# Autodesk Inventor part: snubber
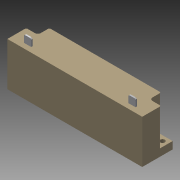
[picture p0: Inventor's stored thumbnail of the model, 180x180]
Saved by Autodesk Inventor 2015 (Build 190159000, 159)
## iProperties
Created: 2016-06
Part Number: snubber
Material: Genérico
Document SubType Name: Modeling
Designer: Diego
Density: 1 g/cm^3
Appearance: Valor por defecto
Author: Diego
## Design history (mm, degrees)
sketch "Boceto1"
  geometry: L1 (0, 0)-(93, 0); L2 (93, 0)-(93, 21); L3 (93, 21)-(0, 21); L4 (0, 21)-(0, 0)
  constraints: 8 end point, 2 parallel, 1 horizontal, 1 perpendicular
  dimensions: "d0" = 93 distance of L3.end L2.end; "d1" = 21 distance of L2.end L1.end
extrude "Extrusión1" new body sketch "Boceto1" distance "d2" = 5; taper "d3" = 0 deg
sketch "Boceto2"
  geometry: L1 (0, 0)-(93, 0) reference; L2 (93, 0)-(93, 21) reference; L3 (93, 21)-(0, 21) reference; L4 (0, 21)-(0, 0) reference; L5 (0, 21)-(8, 21); L6 (8, 21)-(8, 13); L7 (8, 13)-(0, 13); L8 (0, 13)-(0, 21); L9 (93, 21)-(85, 21); L10 (85, 21)-(85, 13); L11 (85, 13)-(93, 13); L12 (93, 13)-(93, 21); 1 further point
  constraints: 16 end point, 4 parallel, 2 horizontal, 2 perpendicular
  dimensions: "d4" = 8 distance of L6.end L7.end; "d5" = 8 distance of L5.end L6.end; "d6" = 8 distance of L11.end L10.end; "d7" = 8 distance of L10.end L9.end
extrude "Extrusión2" join sketch "Boceto2" distance "d8" = 25; taper "d9" = 0 deg
fillet "Empalme1" dims "d10" = 2
fillet "Empalme2" dims "d11" = 2
fillet "Empalme3" dims "d12" = 1
fillet "Empalme4" dims "d13" = 1
fillet "Empalme5" dims "d14" = 1
fillet "Empalme6" dims "d15" = 1
sketch "Boceto3"
  geometry: L1 (1, 13)-(6, 13) reference; 3 further points
hole "Agujero1" sketch "Boceto3" at (89.5, 17.5), (3.5, 17.5) diameter "d16" = 3.25; stored, may be unused: countersink angle "d20" = 90 deg, drill point angle "d22" = 118 deg; dims "d17" = 6, "d18" = 4, "d19" = 2, "d21" = 8
sketch "Boceto4"
  geometry: L1 (13.745, -3.991)-(79.891, -3.991); L2 (79.891, -3.991)-(79.891, -28.068); L3 (79.891, -28.068)-(13.745, -28.068); L4 (13.745, -28.068)-(13.745, -3.991); 1 further point; 1 other entity
  constraints: 2 other
  node "Imagen1"
sketch "Boceto5"
  geometry: L1 (93, 0)-(93, 21) reference; L2 (0, 21)-(0, 0) reference; L3 (84.988, 3.41)-(79.988, 3.41); L4 (79.988, 3.41)-(79.988, 4.41); L5 (79.988, 4.41)-(84.988, 4.41); L6 (84.988, 4.41)-(84.988, 3.41); L7 (0, 0)-(93, 0) reference; L8 (8.012, 3.41)-(13.012, 3.41); L9 (13.012, 3.41)-(13.012, 4.41); L10 (13.012, 4.41)-(8.012, 4.41); L11 (8.012, 4.41)-(8.012, 3.41)
  constraints: 16 end point, 2 parallel, 1 horizontal, 1 perpendicular
  dimensions: "d24" = 5 distance of L4.end L5.end; "d25" = 1 distance of L3.end L4.end
extrude "Extrusión3" join sketch "Boceto5" distance "d26" = 5; taper "d27" = 0 deg
fillet "Empalme7" dims "d28" = 1
fillet "Empalme8" dims "d29" = 1
fillet "Empalme9" dims "d30" = 1
fillet "Empalme10" dims "d31" = 1
node "Sólido1"
node "Contorno proyectado1"
